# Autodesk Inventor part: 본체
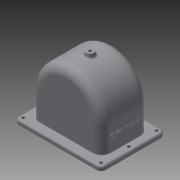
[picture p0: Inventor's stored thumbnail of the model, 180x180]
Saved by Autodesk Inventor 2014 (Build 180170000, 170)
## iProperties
Created: 2015-09
Part Number: 본체
Material: 일반
Document SubType Name: Modeling
Designer: net
Density: 1 g/cm^3
Appearance: 기본값
Author: net
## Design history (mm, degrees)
sketch "스케치1"
  geometry: L1 (-57, 0)-(-57, -40); L2 (57, 0)-(57, -40); L3 (51, 0)-(51, -40); L4 (-51, 0)-(-51, -40); L5 (-57, -40)-(57, -40); A1 r 51 centre (0, 0) between (51, 0) and (-51, 0); A2 r 57 centre (0, 0) between (57, 0) and (-57, 0); 2 further points
  constraints: 10 end point, 5 point on circle, 4 tangent, 3 parallel, 2 centre point, 1 coincident, 1 vertical, 1 vertical alignment
  dimensions: "d1" = 51 radius of A1; "d2" = 6 radial gap between concentric circles of A2 A1; "d7" = 40 distance of L1.start L1.end; "d8" = 40 distance of L2.start L2.end; "d9" = 40 distance of L3.start L3.end; "d10" = 40 distance of L4.start L4.end
extrude "돌출1" new body sketch "스케치1" stored distance "d11" = 77; taper "d12" = 0 deg
fillet "모깎기1" dims "d13" = 14
sketch "스케치3"
  geometry: C1 r 30 at (0, 0); A1 r 43 centre (0, 0) between (-43, 0) and (43, 0) reference
  constraints: 1 centre point, 1 coincident
  dimensions: "d19" = 60 diameter of C1
extrude "돌출2" join sketch "스케치3" distance "d20" = 10; taper "d21" = 0 deg
sketch "스케치4"
  geometry: C1 r 30 at (0, 0) reference; C2 r 20 at (0, 0)
  constraints: 1 centre point, 1 coincident
  dimensions: "d22" = 20 radius of C2
extrude "돌출3" cut sketch "스케치4" distance "d23" = 15; taper "d24" = 0 deg
chamfer "모따기1" distance "d25" = 1; stored, may be unused: second distance "d26" = 2, angle "d27" = 45 deg
node "작업 평면2"
sketch "스케치13"
  geometry: L1 (-63, -52)-(63, -52); L2 (70, -45)-(70, 45); L3 (63, 52)-(-63, 52); L4 (-70, 45)-(-70, -45); L5 (-63, -45)-(-63, 0); L6 (-63, 0)-(63, 0); C1 r 2.5 at (-63, 0); C2 r 2.5 at (63, 0); C3 r 2.5 at (63, -45); C4 r 2.5 at (-63, -45); C5 r 2.5 at (-63, 45); C6 r 2.5 at (63, 45); A1 r 7 centre (63, -45) between (63, -52) and (70, -45); A2 r 7 centre (-63, 45) between (-63, 52) and (-70, 45); A3 r 7 centre (63, 45) between (70, 45) and (63, 52); A4 r 7 centre (-63, -45) between (-70, -45) and (-63, -52); 6 further points
  constraints: 12 end point, 10 centre point, 8 point on circle, 8 tangent, 6 coincident, 6 point on line, 3 equal radius, 3 parallel, 2 midpoint, 2 perpendicular, 1 horizontal, 1 horizontal alignment, 1 vertical alignment
  dimensions: "d38" = 104 distance of point (-70, 52) point (-70, -52); "d39" = 140 distance of point (70, 52) point (-70, 52); "d40" = 7 radius of A1; "d41" = 5 diameter of C1; "d42" = 5 diameter of C2; "d43" = 5 diameter of C3; "d44" = 5 diameter of C4; "d45" = 5 diameter of C5; "d46" = 5 diameter of C6
extrude "돌출4" join sketch "스케치13" distance "d47" = 7; taper "d48" = 0 deg
fillet "모깎기2" dims "d49" = 1
fillet "모깎기3" dims "d50" = 3
node "작업 평면3"
node "작업 평면4"
sketch "스케치15"
  geometry: C1 r 6 at (0, 24.5); 1 further point
  constraints: 1 centre point, 1 coincident
  dimensions: "d62" = 12 diameter of C1
extrude "돌출5" join sketch "스케치15" stored distance "d63" = 8; taper "d64" = 10 deg
fillet "모깎기4" dims "d65" = 3
hole "구멍1" diameter "d68" = 4.134; stored, may be unused: countersink angle "d72" = 90 deg, drill point angle "d74" = 0 deg; dims "d66" = 10, "d67" = 10, "d69" = 11, "d70" = 4, "d71" = 2, "d73" = 11
sketch "스케치16" dims "d75" = 48
  geometry: C1 r 21 at (0, 0) reference; 2 further points
  constraints: 1 coincident, 1 vertical alignment, 2 other
hole "구멍2" sketch "스케치16" at (0, 24) diameter "d76" = 3.242; stored, may be unused: countersink angle "d80" = 90 deg, drill point angle "d82" = 118 deg; dims "d77" = 6, "d78" = 4, "d79" = 2, "d81" = 8
sketch "스케치17"
  geometry: L1 (0, 0)-(0, 49) reference; L2 (47, -27.5)-(47, -20.5) reference; 3 further points
  constraints: 1 horizontal alignment, 1 midpoint, 1 other
  dimensions: "d86" = 30 distance from line of L2 point (17, 24.5)
feature "엠보싱1" sketch "스케치17" dims "d87" = 0.5, "d88" = 0
sketch "스케치32"
  geometry: L1 (-38.5, 0)-(-38.5, 43) reference; L2 (-38.5, -39)-(-38.5, 0) reference; L3 (-45, -47)-(45, -47) reference; L4 (-24.5, 57)-(24.5, 57) reference; L5 (38.5, 43)-(38.5, 0) reference; L6 (33.5, -47)-(33.5, 41.165); L7 (24.5, 50.165)-(-24.5, 50.165); L8 (-33.5, 41.165)-(-17.81, 28); L9 (-17.81, 28)-(-17.81, -28); L10 (-17.81, -28)-(-33.5, -41.165); L11 (-33.5, -41.165)-(-33.5, -47); L12 (-38.5, 0)-(33.5, 0); A1 r 9 centre (-24.5, 41.165) between (-24.5, 50.165) and (-33.5, 41.165); A2 r 9 centre (24.5, 41.165) between (33.5, 41.165) and (24.5, 50.165); 4 further points
  constraints: 14 end point, 4 perpendicular, 4 point on circle, 3 point on line, 3 tangent, 2 centre point, 2 horizontal alignment, 2 midpoint, 1 equal radius, 1 parallel, 1 vertical alignment
  dimensions: "d105" = 9 radius of A1; "d106" = 5 distance between parallel lines of L5 L6; "d107" = 56 diameter of L8.end L12; "d108" = 50 deg angle of L9 L8; "d109" = 50 deg angle of L9 L10; "d112" = 5 distance from line of L1 L8.start; "d113" = 5 distance between parallel lines of L11 L2
sketch "스케치31"
  geometry: 1 further point
node "솔리드1"
pattern_circular "원형 패턴1" dims angle "d84" = 360 deg
other parameters: "d37" = -47, "d61" = 6
